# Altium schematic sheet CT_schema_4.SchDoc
size 289 x 230 mm
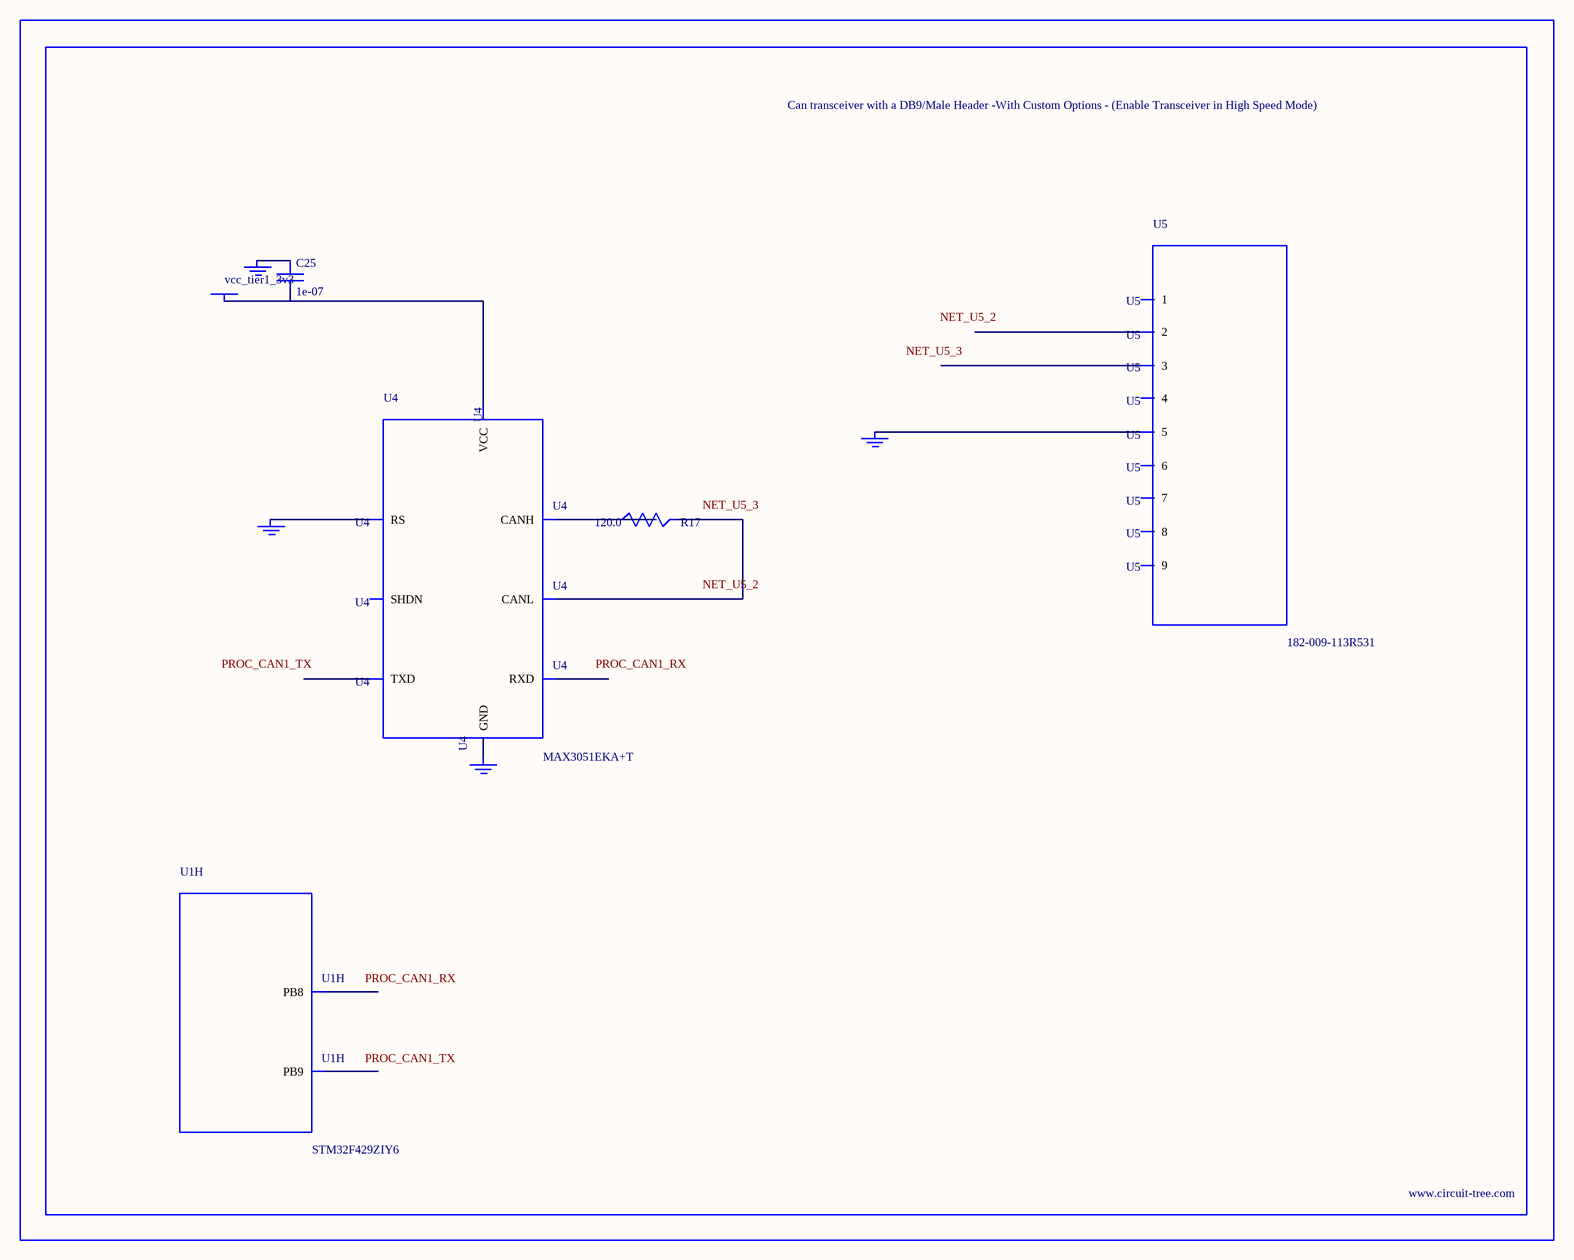
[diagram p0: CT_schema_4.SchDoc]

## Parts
BORDER3  (no value)
C25  1e-07  [C0402]
GND_INSTANCE_3_0  (no value)
GND_INSTANCE_3_1  (no value)
GND_INSTANCE_3_2  (no value)
GND_INSTANCE_3_3  (no value)
POWER_INSTANCE_3_0  vcc_tier1_3v3
R17  120.0  [R0603]
U1  STM32F429ZIY6  [WLCSP143]  (part H of 13)
U4  MAX3051EKA+T  [SOT-23-8]
U5  182-009-113R531  [182-009-MALE]

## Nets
NetC25_1: C25.1 GND_INSTANCE_3_0.0(GND)
NetC25_2: C25.2 POWER_INSTANCE_3_0.0(PWR) U4.3(VCC)
NetGND_INSTANCE_3_1_0: GND_INSTANCE_3_1.0(GND) U4.8(RS)
NetGND_INSTANCE_3_2_0: GND_INSTANCE_3_2.0(GND) U4.2(GND)
NetGND_INSTANCE_3_3_0: GND_INSTANCE_3_3.0(GND) U5.5
NetR17_1: R17.1 U4.7(CANH)
NetR17_2: R17.2 U4.6(CANL)

Not connected (* = marked no-connect by the designer): U1 A9(PB8) B9(PB9); U4 1(TXD) 4(RXD) 5(SHDN); U5 1 2 3 4 6 7 8 9

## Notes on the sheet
- Labels drawn without touching a wire or pin: NET_U5_2, NET_U5_3, PROC_CAN1_RX, PROC_CAN1_TX

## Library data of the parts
BORDER3 = BORDER_PAGE3
C25 = C0402C104K3RACTU
GND_INSTANCE_3_0-GND_INSTANCE_3_3 = GND
POWER_INSTANCE_3_0 = PWR
R17 = RC0603JR-07120RL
